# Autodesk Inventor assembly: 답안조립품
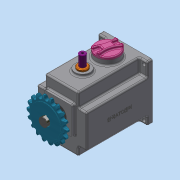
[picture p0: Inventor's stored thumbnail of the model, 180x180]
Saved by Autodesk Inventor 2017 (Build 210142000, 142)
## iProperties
Part Number: 답안조립품
Material: 일반
Document SubType Name: Assembly
Designer: MRC
Author: MRC
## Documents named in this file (16)
- C:\Users\MRC\Desktop\720212V1004\답안조립품.iam
- C:\Users\MRC\Desktop\720212V1004\본체.ipt
- C:\Users\MRC\Desktop\720212V1004\멈춤나사 M3.ipt
- C:\Users\MRC\Desktop\720212V1004\메인 축.ipt
- C:\Users\MRC\Desktop\720212V1004\베어링 608.ipt
- C:\Users\MRC\Desktop\720212V1004\베어링 6003.ipt
- C:\Users\MRC\Desktop\720212V1004\볼트 M4 x 10.ipt
- C:\Users\MRC\Desktop\720212V1004\부시.ipt
- C:\Users\MRC\Desktop\720212V1004\상부 캡.ipt
- C:\Users\MRC\Desktop\720212V1004\서브 축.ipt
- C:\Users\MRC\Desktop\720212V1004\스프로킷.ipt
- C:\Users\MRC\Desktop\720212V1004\슬라이더.ipt
- C:\Users\MRC\Desktop\720212V1004\오일 실 8 x 22 x 7.ipt
- C:\Users\MRC\Desktop\720212V1004\오일 실 17 x 32 x 8.ipt
- C:\Users\MRC\Desktop\720212V1004\커버.ipt
- C:\Users\MRC\Desktop\720212V1004\키 5 x 5.ipt
